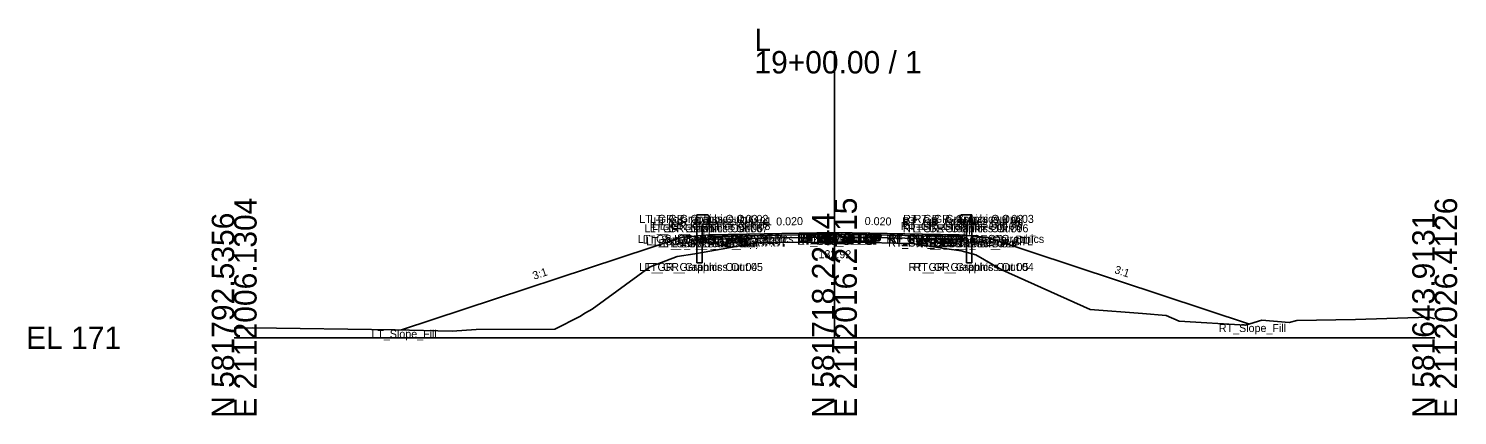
# Model space of a CAD drawing. Extents: x -26 to 3453, y -333 to 9539.
# Drawn here: x -25.7 to 152.8, y 9490.3 to 9538.6 of the extents above; entities that cross this region are included whole.
import ezdxf

# ---------------------------------------------------------------- set-up
doc = ezdxf.new("R2010")
doc.units = 0
for name, color, linetype in [('Default', 7, 'Continuous'), ('Exist Cross Section Cell', 7, 'Continuous'), ('Exist XS Center Line Elevation Label', 7, 'Continuous'), ('Exist XS Ground Line', 7, 'Continuous'), ('Prop CMT Guardrail Graphics', 7, 'Continuous'), ('Prop CMT Pvmt Course 1', 7, 'Continuous'), ('Prop CMT Pvmt Course 2', 7, 'Continuous'), ('Prop CMT Pvmt Course 3', 7, 'Continuous'), ('Prop CMT Pvmt Surface', 7, 'Continuous'), ('Prop CMT Pvmt Surface Shoulder', 7, 'Continuous'), ('Prop CMT Shld Paved Course 1', 7, 'Continuous'), ('Prop CMT Shld Paved Course 2', 7, 'Continuous'), ('Prop CMT Shld Paved Course 3', 7, 'Continuous'), ('Prop CMT Slope Grass', 7, 'Continuous'), ('Prop CMT Subgrade Earthwork', 7, 'Continuous'), ('Prop XS SE Text', 7, 'Continuous'), ('Prop XS Side Slope Text', 7, 'Continuous'), ('Scratch_Level_0', 7, 'Continuous')]:
    doc.layers.add(name, color=color, linetype=linetype)

msp = doc.modelspace()

# ---------------------------------------------------------------- linework, layer by layer
at = {"layer": 'Exist Cross Section Cell'}
for p, q in [((75, 9500), (75, 9535.78)), ((0, 9500), (75, 9500)), ((75, 9500), (150, 9500))]:
    msp.add_line(p, q, dxfattribs=at)
at = {"layer": 'Exist XS Ground Line'}
for p, q in [((55.35, 9510.12), (57.55, 9510.48)), ((57.55, 9510.48), (65.29, 9511.86)), ((65.29, 9511.86), (67.67, 9511.88)), ((67.67, 9511.88), (74.62, 9511.93)), ((74.62, 9511.93), (75, 9511.92)), ((75, 9511.92), (77.19, 9511.91)), ((77.19, 9511.91), (84.63, 9511.74)), ((84.63, 9511.74), (88.76, 9511.15)), ((88.76, 9511.15), (90.85, 9510.85)), ((90.85, 9510.85), (92.66, 9510.34)), ((44.71, 9503.57), (51.96, 9508.84)), ((51.96, 9508.84), (55.35, 9510.12)), ((92.66, 9510.34), (95.93, 9508.47)), ((95.93, 9508.47), (106.94, 9503.51)), ((43.89, 9503.11), (44.71, 9503.57)), ((106.94, 9503.51), (113.48, 9503.04)), ((40.07, 9501.07), (43.2, 9502.64)), ((43.2, 9502.64), (43.89, 9503.11)), ((113.48, 9503.04), (116.45, 9502.76)), ((116.45, 9502.76), (118.09, 9502.06)), ((118.09, 9502.06), (126.36, 9501.56)), ((126.36, 9501.56), (128.39, 9502.21)), ((128.39, 9502.21), (131.81, 9501.88)), ((131.81, 9501.88), (132.77, 9502.17)), ((132.77, 9502.17), (140.09, 9502.26)), ((140.09, 9502.26), (149.25, 9502.57)), ((149.25, 9502.57), (150, 9502.37)), ((0, 9501.2), (0.37, 9501.19)), ((0.37, 9501.19), (2.31, 9501.24)), ((2.31, 9501.24), (20.13, 9500.99)), ((20.13, 9500.99), (27.23, 9500.8)), ((27.23, 9500.8), (30.22, 9501.04)), ((30.22, 9501.04), (40.07, 9501.07))]:
    msp.add_line(p, q, dxfattribs=at)
at = {"layer": 'Prop CMT Guardrail Graphics'}
for points in [[(57.82, 9509.33), (57.82, 9515.33)], [(57.82, 9515.33), (59.16, 9515.33), (59.43, 9515.04)], [(59.43, 9514.45), (59.16, 9514.16), (58.49, 9514.16)], [(58.49, 9514.16), (58.49, 9509.33)], [(59.43, 9515.04), (59.16, 9514.74)], [(59.16, 9514.74), (59.43, 9514.45)], [(92.18, 9515.33), (90.84, 9515.33), (90.57, 9515.04)], [(90.57, 9515.04), (90.84, 9514.74)], [(90.84, 9514.74), (90.57, 9514.45)], [(90.57, 9514.45), (90.84, 9514.16), (91.51, 9514.16)], [(91.51, 9514.16), (91.51, 9509.33)], [(92.18, 9509.33), (92.18, 9515.33)], [(58.49, 9509.33), (57.82, 9509.33)], [(91.51, 9509.33), (92.18, 9509.33)]]:
    msp.add_lwpolyline(points, dxfattribs=at)
at = {"layer": 'Prop CMT Pvmt Course 1'}
for points in [[(75, 9513.14), (64, 9512.92)], [(64, 9512.71), (75, 9512.93)], [(64, 9512.92), (64, 9512.71)], [(75, 9512.93), (75, 9513.14)], [(75, 9513.14), (86, 9512.92)], [(75, 9512.93), (75, 9513.14)], [(86, 9512.71), (75, 9512.93)], [(86, 9512.92), (86, 9512.71)]]:
    msp.add_lwpolyline(points, dxfattribs=at)
msp.add_lwpolyline([(75, 9512.93), (75, 9513.02), (75, 9513.02), (75, 9512.93)], close=True, dxfattribs=at)
msp.add_lwpolyline([(75, 9512.93), (75, 9513.02), (75, 9513.02), (75, 9512.93)], close=True, dxfattribs=at)
at = {"layer": 'Prop CMT Pvmt Course 2'}
for points in [[(75, 9512.93), (64, 9512.71)], [(64, 9512.71), (64, 9512.38)], [(64, 9512.38), (75, 9512.6)], [(75, 9512.6), (75, 9512.93)], [(75, 9512.6), (75, 9512.93)], [(75, 9512.93), (86, 9512.71)], [(86, 9512.38), (75, 9512.6)], [(86, 9512.71), (86, 9512.38)]]:
    msp.add_lwpolyline(points, dxfattribs=at)
at = {"layer": 'Prop CMT Pvmt Course 3'}
for points in [[(75, 9512.6), (64, 9512.38)], [(64, 9512.38), (75, 9512.6)], [(64, 9512.38), (64, 9512.38)], [(75, 9512.6), (75, 9512.6)], [(75, 9512.6), (86, 9512.38)], [(86, 9512.38), (75, 9512.6)], [(75, 9512.6), (75, 9512.6)], [(86, 9512.38), (86, 9512.38)]]:
    msp.add_lwpolyline(points, dxfattribs=at)
at = {"layer": 'Prop CMT Pvmt Surface'}
for points in [[(75, 9513.14), (64, 9512.92)], [(75, 9513.14), (86, 9512.92)]]:
    msp.add_lwpolyline(points, dxfattribs=at)
at = {"layer": 'Prop CMT Pvmt Surface Shoulder'}
for points in [[(64, 9512.92), (59.44, 9512.83)], [(86, 9512.92), (90.56, 9512.83)]]:
    msp.add_lwpolyline(points, dxfattribs=at)
at = {"layer": 'Prop CMT Shld Paved Course 1'}
for points in [[(64, 9512.92), (59.44, 9512.83), (59.22, 9512.62)], [(59.22, 9512.62), (64, 9512.71)], [(64, 9512.71), (64, 9512.92)], [(86, 9512.92), (90.56, 9512.83), (90.78, 9512.62)], [(86, 9512.71), (86, 9512.92)], [(90.78, 9512.62), (86, 9512.71)]]:
    msp.add_lwpolyline(points, dxfattribs=at)
at = {"layer": 'Prop CMT Shld Paved Course 2'}
for points in [[(64, 9512.71), (59.22, 9512.62), (58.88, 9512.28)], [(58.88, 9512.28), (64, 9512.38)], [(64, 9512.38), (64, 9512.71)], [(86, 9512.71), (90.78, 9512.62), (91.12, 9512.28)], [(86, 9512.38), (86, 9512.71)], [(91.12, 9512.28), (86, 9512.38)]]:
    msp.add_lwpolyline(points, dxfattribs=at)
at = {"layer": 'Prop CMT Shld Paved Course 3'}
for points in [[(64, 9512.38), (58.88, 9512.28)], [(58.88, 9512.28), (64, 9512.38)], [(58.88, 9512.28), (58.88, 9512.28), (58.88, 9512.28)], [(64, 9512.38), (64, 9512.38)], [(86, 9512.38), (91.12, 9512.28)], [(91.12, 9512.28), (86, 9512.38)], [(86, 9512.38), (86, 9512.38)], [(91.12, 9512.28), (91.12, 9512.28), (91.12, 9512.28)]]:
    msp.add_lwpolyline(points, dxfattribs=at)
at = {"layer": 'Prop CMT Slope Grass'}
for points in [[(56, 9512.55), (20.91, 9500.97)], [(59.43, 9512.83), (56, 9512.55)], [(59.44, 9512.83), (59.43, 9512.83)], [(90.56, 9512.83), (90.57, 9512.83)], [(90.57, 9512.83), (94, 9512.55)], [(94, 9512.55), (126.85, 9501.71)]]:
    msp.add_lwpolyline(points, dxfattribs=at)
at = {"layer": 'Prop CMT Subgrade Earthwork'}
for points in [[(58.88, 9512.28), (58.41, 9512.75)], [(64, 9512.38), (58.88, 9512.28)], [(75, 9512.6), (64, 9512.38)], [(75, 9512.6), (86, 9512.38)], [(86, 9512.38), (91.12, 9512.28)], [(91.12, 9512.28), (91.59, 9512.75)]]:
    msp.add_lwpolyline(points, dxfattribs=at)

# ---------------------------------------------------------------- texts
at = {"layer": 'Default'}
msp.add_text('-', height=0.0001, dxfattribs=at).set_placement((0, 9500))
at = {"layer": 'Exist Cross Section Cell'}
for s, p in [('L', (65, 9535.78)), ('19+00.00 / 1', (65, 9532.98)), ('EL 171', (-26, 9498.6))]:
    msp.add_text(s, height=2.8, dxfattribs=at).set_placement(p)
for s, p in [('E 2112006.1304', (2.8, 9490)), ('E 2112016.2715', (77.8, 9490)), ('E 2112026.4126', (152.8, 9490)), ('N 581792.5356', (0, 9490)), ('N 581718.2244', (75, 9490)), ('N 581643.9131', (150, 9490))]:
    msp.add_text(s, height=2.8, rotation=90, dxfattribs=at).set_placement(p)
at = {"layer": 'Exist XS Center Line Elevation Label'}
msp.add_text('182.92', height=1, dxfattribs=at).set_placement((73.01, 9509.92))
at = {"layer": 'Prop XS SE Text'}
for rotation, p in [(1.1458, (67.73, 9514)), (358.8542, (78.77, 9514.07))]:
    msp.add_text('0.020', height=1, rotation=rotation, dxfattribs=at).set_placement(p)
at = {"layer": 'Prop XS Side Slope Text'}
for rotation, p in [(18.2629, (37.47, 9507.23)), (341.7371, (109.91, 9508.09))]:
    msp.add_text('3:1', height=1, rotation=rotation, dxfattribs=at).set_placement(p)
at = {"layer": 'Scratch_Level_0'}
for s, p in [('LT_GR_Graphics Out 03', (50.61, 9514.33)), ('LT_GR_Graphics Out 06', (51.26, 9513.16)), ('LT_GR_Graphics Out 07', (51.92, 9513.16)), ('LT_GR_Graphics Out 09', (51.93, 9513.74)), ('LT_GR_Graphics Out 02', (51.96, 9514.33)), ('LT_GR_Graphics Out 08', (52.2, 9513.45)), ('LT_GR_Graphics Out 01', (52.37, 9514.04)), ('RT_GR_Graphics Out 08', (83.28, 9513.45)), ('RT_GR_Graphics Out 01', (83.46, 9514.04)), ('RT_GR_Graphics Out 07', (83.54, 9513.16)), ('RT_GR_Graphics Out 09', (83.56, 9513.74)), ('RT_GR_Graphics Out 02', (83.59, 9514.33)), ('RT_GR_Graphics Out 06', (84.22, 9513.16)), ('RT_GR_Graphics Out 03', (84.9, 9514.33)), ('LT_GS_OS_GR_Face_Graphics', (50.42, 9511.83)), ('LT_Sub_Trench_Out_DLT', (51.06, 9511.75)), ('LT_GS_OS_CTL', (51.46, 9511.55)), ('LT_Sub_Trench_Out', (52.99, 9511.28)), ('LT_PS3_Shelf_Out', (53.54, 9511.28)), ('LT_PS3_OEOP', (54.67, 9511.28)), ('LT_PS2_OEOP', (55.01, 9511.62)), ('LT_PS1_OEOP', (55.34, 9511.83)), ('LT_PV2_OEOT', (59.75, 9511.71)), ('LT_PV3_OEOT', (59.75, 9511.38)), ('LT_Sub_OEOT', (59.77, 9511.38)), ('LT_PV1_OEOT', (59.87, 9511.92)), ('RT_PV2_OEEOP', (70.33, 9511.93)), ('RT_PV3_OEEOP', (70.33, 9511.6)), ('RT_Sub_OEEOP', (70.36, 9511.6)), ('LT_PV2_OEEOP', (70.39, 9511.93)), ('LT_PV3_OEEOP', (70.39, 9511.6)), ('LT_Sub_OEEOP', (70.42, 9511.6)), ('RT_PV1_OEEOP', (70.45, 9512.02)), ('LT_PV1_OEEOP', (70.51, 9512.02)), ('RT_PV2_IEEOP', (70.71, 9511.93)), ('LT_PV2_IEEOP', (70.77, 9511.93)), ('RT_PV1_IEEOP', (70.83, 9512.02)), ('LT_PV1_IEEOP', (70.89, 9512.02)), ('PV2_PGL', (72.35, 9511.93)), ('PV1_PGL', (72.47, 9512.14)), ('RT_GS_OS_GR_Face_Graphics', (81.51, 9511.83)), ('RT_PV2_OEOT', (81.69, 9511.71)), ('RT_PV3_OEOT', (81.69, 9511.38)), ('RT_Sub_OEOT', (81.71, 9511.38)), ('RT_PV1_OEOT', (81.81, 9511.92)), ('RT_Sub_Trench_Out_DLT', (84.18, 9511.75)), ('RT_Sub_Trench_Out', (85.17, 9511.28)), ('RT_PS3_Shelf_Out', (85.71, 9511.28)), ('RT_PS1_OEOP', (86.41, 9511.83)), ('RT_PS2_OEOP', (86.5, 9511.62)), ('RT_PS3_OEOP', (86.84, 9511.28)), ('RT_GS_OS_CTL', (89.4, 9511.55)), ('LT_GR_Graphics Out 04', (50.59, 9508.33)), ('LT_GR_Graphics Out 05', (51.27, 9508.33)), ('RT_GR_Graphics Out 05', (84.23, 9508.33)), ('RT_GR_Graphics Out 04', (84.89, 9508.33)), ('RT_Slope_Fill', (123.03, 9500.71)), ('LT_Slope_Fill', (17.14, 9499.97))]:
    msp.add_text(s, height=1, dxfattribs=at).set_placement(p)

doc.saveas('drawing.dxf')
